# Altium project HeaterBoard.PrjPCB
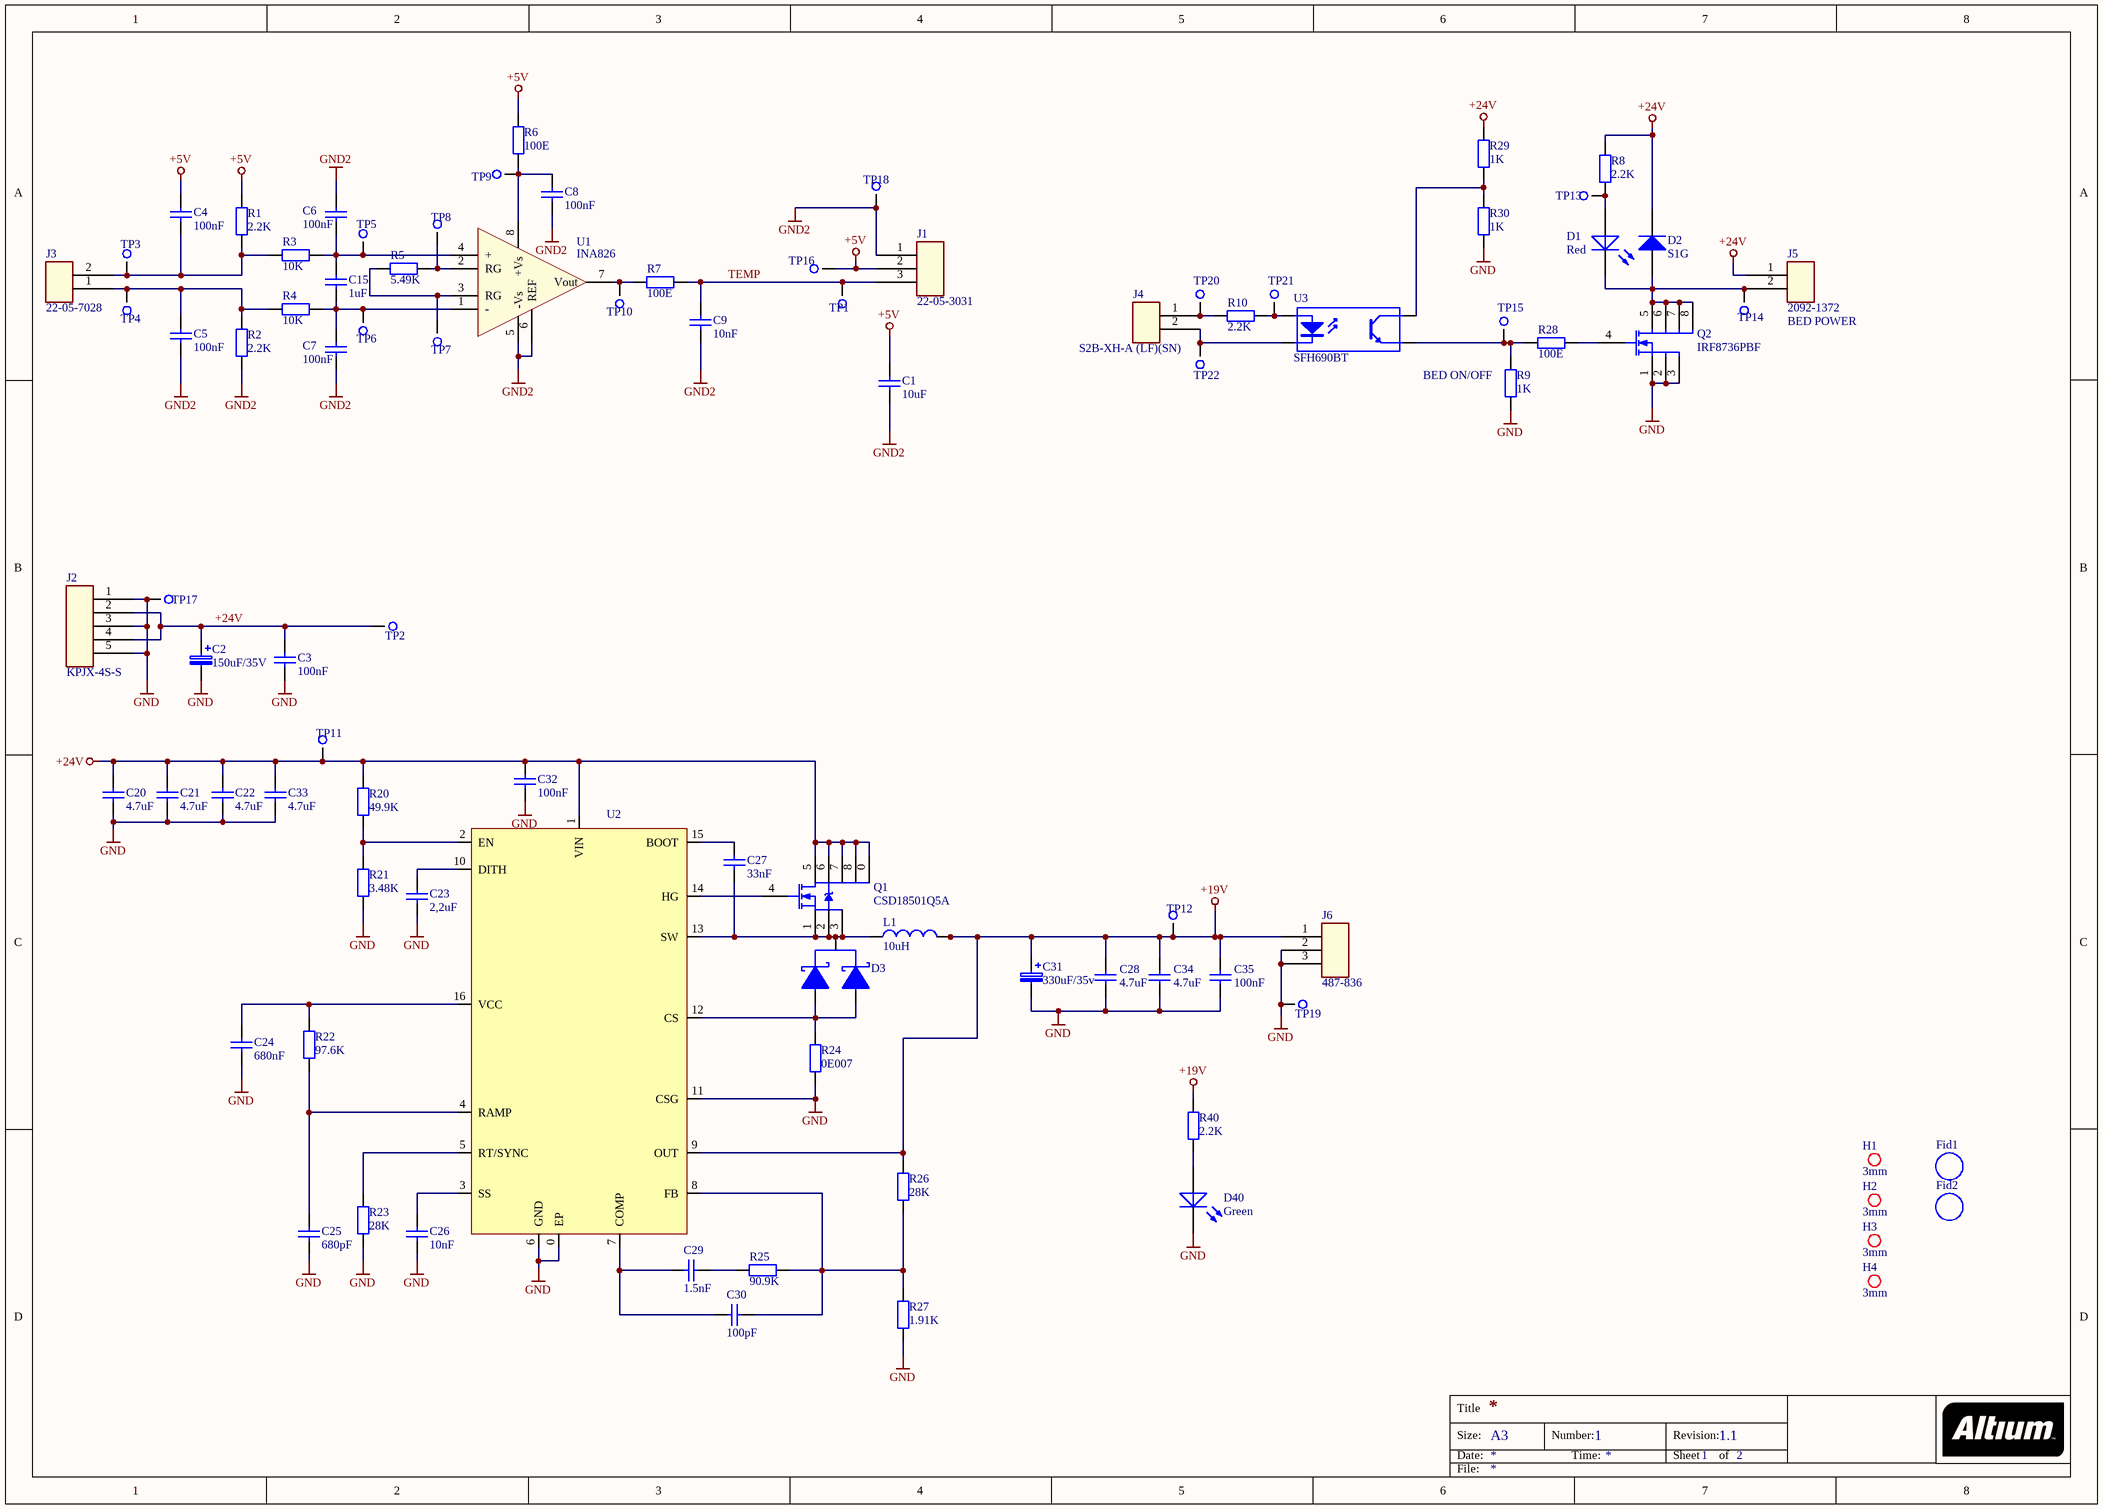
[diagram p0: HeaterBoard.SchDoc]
1 sheet, 92 parts. Net scope: global (net labels, ports and power ports of the same name join across sheets).
Board file: HeaterBoard.PcbDoc

## Sheet HeaterBoard.SchDoc
size A3; ApprovedBy: CdB; CheckedBy: CdB; DrawnBy: RT; Engineer: CdB; DocumentNumber: 1; Revision: 1.1; SheetNumber: 1; SheetTotal: 2; Status: Final

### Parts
C1  10uF  [C1206 (3216)]
C2  150uF/35V  [ELCO Case F]
C3  100nF  [C0805 (2012)]
C4  100nF  [C0805 (2012)]
C5  100nF  [C0805 (2012)]
C6  100nF  [C0805 (2012)]
C7  100nF  [C0805 (2012)]
C8  100nF  [C0805 (2012)]
C9  10nF  [C0805 (2012)]
C15  1uF  [C0603 (1608)]
C20  4.7uF  [C1206 (3216)]
C21  4.7uF  [C1206 (3216)]
C22  4.7uF  [C1206 (3216)]
C23  2,2uF  [C0603 (1608)]
C24  680nF  [C0603 (1608)]
C25  680pF  [C0603 (1608)]
C26  10nF  [C0603 (1608)]
C27  33nF  [C0805 (2012)]
C28  4.7uF  [C1206 (3216)]
C29  1.5nF  [C0603 (1608)]
C30  100pF  [C0603 (1608)]
C31  330uF/35v  [ELCO Case G]
C32  100nF  [C0805 (2012)]
C33  4.7uF  [C1206 (3216)]
C34  4.7uF  [C1206 (3216)]
C35  100nF  [C0805 (2012)]
D1  Red  [LED0805-RED]
D2  S1G  [DIODE DO214AC (SMA)]
D3  Diode Dual Schottky MBRB1545 45V 15A  [DIODE D2PAK(Case 418B)]  (value not drawn)
D40  Green  [LED0805-GREEN]
Fid1  Fiducial  [Fiducial 1,5mm]  (value not drawn)  (no BOM)
Fid2  Fiducial  [Fiducial 1,5mm]  (value not drawn)  (no BOM)
H1  3mm  [Mounting Hole 3mm NPTH]  (no BOM)
H2  3mm  [Mounting Hole 3mm NPTH]  (no BOM)
H3  3mm  [Mounting Hole 3mm NPTH]  (no BOM)
H4  3mm  [Mounting Hole 3mm NPTH]  (no BOM)
J1  22-05-3031  [HEADER 3P RIGHT ANGLE]
J2  KPJX-4S-S  [Con KPJX-4S-S]
J3  22-05-7028  [HEADER 2P RIGHT ANGLE]
J4  S2B-XH-A (LF)(SN)  [CON S2B-XH-A (LF)(SN)]
J5  2092-1372  [Con 2092-1372]
J6  487-836  [Con DC Power Socket]
L1  10uH  [Inductor XAL1010-103MEB]
Q1  CSD18501Q5A  [IC SON5x6]
Q2  IRF8736PBF  [IC SOIC-8]
R1  2.2K  [R0805 (2012)]
R2  2.2K  [R0805 (2012)]
R3  10K  [R0805 (2012)]
R4  10K  [R0805 (2012)]
R5  5.49K  [R0603 (1608)]
R6  100E  [R0805 (2012)]
R7  100E  [R0805 (2012)]
R8  2.2K  [R0805 (2012)]
R9  1K  [R0805 (2012)]
R10  2.2K  [R0805 (2012)]
R20  49.9K  [R0603 (1608)]
R21  3.48K  [R0603 (1608)]
R22  97.6K  [R0603 (1608)]
R23  28K  [R0603 (1608)]
R24  0E007  [R1632X06N]
R25  90.9K  [R0603 (1608)]
R26  28K  [R0603 (1608)]
R27  1.91K  [R0603 (1608)]
R28  100E  [R0805 (2012)]
R29  1K  [R0805 (2012)]
R30  1K  [R0805 (2012)]
R40  2.2K  [R0805 (2012)]
TP1  2mm  [TESTPOINT 2mm]  (value not drawn)  (no BOM)
TP2  2mm  [TESTPOINT 2mm]  (value not drawn)  (no BOM)
TP3  2mm  [TESTPOINT 2mm]  (value not drawn)  (no BOM)
TP4  2mm  [TESTPOINT 2mm]  (value not drawn)  (no BOM)
TP5  2mm  [TESTPOINT 2mm]  (value not drawn)  (no BOM)
TP6  2mm  [TESTPOINT 2mm]  (value not drawn)  (no BOM)
TP7  2mm  [TESTPOINT 2mm]  (value not drawn)  (no BOM)
TP8  2mm  [TESTPOINT 2mm]  (value not drawn)  (no BOM)
TP9  2mm  [TESTPOINT 2mm]  (value not drawn)  (no BOM)
TP10  2mm  [TESTPOINT 2mm]  (value not drawn)  (no BOM)
TP11  2mm  [TESTPOINT 2mm]  (value not drawn)  (no BOM)
TP12  2mm  [TESTPOINT 2mm]  (value not drawn)  (no BOM)
TP13  2mm  [TESTPOINT 2mm]  (value not drawn)  (no BOM)
TP14  2mm  [TESTPOINT 2mm]  (value not drawn)  (no BOM)
TP15  2mm  [TESTPOINT 2mm]  (value not drawn)  (no BOM)
TP16  2mm  [TESTPOINT 2mm]  (value not drawn)  (no BOM)
TP17  2mm  [TESTPOINT 2mm]  (value not drawn)  (no BOM)
TP18  2mm  [TESTPOINT 2mm]  (value not drawn)  (no BOM)
TP19  2mm  [TESTPOINT 2mm]  (value not drawn)  (no BOM)
TP20  2mm  [TESTPOINT 2mm]  (value not drawn)  (no BOM)
TP21  2mm  [TESTPOINT 2mm]  (value not drawn)  (no BOM)
TP22  2mm  [TESTPOINT 2mm]  (value not drawn)  (no BOM)
U1  INA826  [IC MSOP8]
U2  LM25088MH-1  [IC HTSSOP-16]  (value not drawn)
U3  SFH690BT  [IC SOP-4]

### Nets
+5V: C1.2 C4.1 J1.2 R1.2 R6.2 TP16.1
+19V: C28.2 C31.1 C34.2 C35.1 J6.1 L1.2 R26.2 R40.2 TP12.1 U2.9(OUT)
+24V: C2.1 C3.1 C20.2 C21.2 C22.2 C32.1 C33.2 D2.2(K) J2.2 J2.4 J5.1 Q1.0(D) Q1.5(D) Q1.6(D) Q1.7(D) Q1.8(D) R8.2 R20.2 R29.2 TP2.1 TP11.1 U2.1(VIN)
GND: C2.2 C3.2 C20.1 C21.1 C22.1 C23.1 C24.1 C25.1 C26.1 C28.1 C31.2 C32.2 C33.1 C34.1 C35.2 D40.2(K) J2.1 J2.3 J2.5 J6.2 J6.3 Q2.1(S) Q2.2(S) Q2.3(S) R9.1 R21.1 R23.1 R24.1 R27.1 R30.2 TP17.1 TP19.1 U2.0(EP) U2.6(GND) U2.11(CSG)
GND2: C1.1 C5.2 C6.1 C7.2 C8.2 C9.1 J1.1 R2.1 TP18.1 U1.5(-Vs) U1.6(REF)
TEMP: C9.2 J1.3 R7.1 TP1.1
NetC4_2: C4.2 J3.2 R1.1 R3.1 TP3.1
NetC5_1: C5.1 J3.1 R2.2 R4.1 TP4.1
NetC6_2: C6.2 C15.2 R3.2 TP5.1 U1.4(+)
NetC7_1: C7.1 C15.1 R4.2 TP6.1 U1.1(-)
NetC8_1: C8.1 R6.1 TP9.1 U1.8(+Vs)
NetC23_2: C23.2 U2.10(DITH)
NetC24_2: C24.2 R22.2 U2.16(VCC)
NetC25_2: C25.2 R22.1 U2.4(RAMP)
NetC26_2: C26.2 U2.3(SS)
NetC27_1: C27.1 D3.4(K) L1.1 Q1.1(S) Q1.2(S) Q1.3(S) U2.13(SW)
NetC27_2: C27.2 U2.15(BOOT)
NetC29_1: C29.1 C30.1 U2.7(COMP)
NetC29_2: C29.2 R25.1
NetC30_2: C30.2 R25.2 R26.1 R27.2 U2.8(FB)
NetD1_1: D1.1(A) R8.1 TP13.1
NetD1_2: D1.2(K) D2.1(A) J5.2 Q2.5(D) Q2.6(D) Q2.7(D) Q2.8(D) TP14.1
NetD3_1: D3.1(A) D3.3(A) R24.2 U2.12(CS)
NetD40_1: D40.1(A) R40.1
NetJ4_1: J4.1 R10.1 TP20.1
NetJ4_2: J4.2 TP22.1 U3.2(K)
NetQ1_4: Q1.4 U2.14(HG)
NetQ2_4: Q2.4(G) R28.2
NetR5_1: R5.1 TP7.1 U1.3(RG)
NetR5_2: R5.2 TP8.1 U1.2(RG)
NetR7_2: R7.2 TP10.1 U1.7(Vout)
NetR9_2: R9.2 R28.1 TP15.1 U3.3(E)
NetR10_2: R10.2 TP21.1 U3.1(A)
NetR20_1: R20.1 R21.2 U2.2(EN)
NetR23_2: R23.2 U2.5(RT/SYNC)
NetR29_1: R29.1 R30.1 U3.4(C)

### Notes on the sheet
- BED ON/OFF
- (near J5) BED POWER

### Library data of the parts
C1 = Cap 10uF X7R 1206: Cap 10uF X7R 1206  10% 25V; Faber ItemCode: 35605200; Mfg: SAMSUNG; Mfg code: CL31B1076KAHNNNE; Faber Artikelomschrijving: X7R 10uF 10% 25V 1206; Bestel grote: 2000; Prijs: 0,0218
C2 = Cap Elco 150uF 35V: Cap elco 150uF 35V case F  EEHZA1 PAN; Value: 135uF/35V; Bestel grote: 10; Mfg: PANASONIC; Mfg code: EEHZA1V151P; Prijs: 2,03
C3-C8 C32 C35 = Cap 100nF X7R 0805: Cap 100nF X7R 0805 10% 50V; Faber ItemCode: 31219200; Mfg: PHYCOMP; Mfg code: 2238 580 15649; Faber Artikelomschrijving: X7R 100nF 10% 50V 0805; Bestel grote: 4000; Prijs: 0,0032
C9 = Cap 10nF X7R 0805: Cap 10nF X7R 0805 10% 50V; Faber ItemCode: 30873000; Mfg: PHYCOMP; Mfg code: 2238 580 15636; Faber Artikelomschrijving: X7R 10nF 10% 50V 0805; Bestel grote: 24000; Prijs: 0,002
C15 = Cap 1uF X5R 0603: Cap 1uF X5R 0603 10% 10V; Faber ItemCode: 36310600; Faber Artikelomschrijving: X5R 1uF 10% 10V 0603; Prijs: 0,0028
C20-C22 C28 C33 C34 = Cap 4.7uF 50V X7R 1206: Cap 4.7uF X7R 1206 10% 50V; Mfg: MURATA; Mfg code: GRM31CR71H475KA12L; Bestel grote: 10; Prijs: 0,49
C23 = Cap 2,2uF X7R 0603: Cap 2,2uF X7R 0603 10% 6,3V; Faber ItemCode: 35496900; Faber Artikelomschrijving: X7R 2,2UF 10% 6,3V 0603; Prijs: 0,0081
C24 = Cap 680nF X7R 0603: Cap 680nF X7R 0603 10% 16V; Faber ItemCode: 35550500; Faber Artikelomschrijving: X7R 680NF 10% 16V 0603; Prijs: 0,124
C25 = Cap 680pF X7R 0603: Cap 680pF NPO 0603 5% 50V; Mfg: MULTICOMP; Mfg code: MC0603N681J500CT; Bestel grote: 10; Prijs: 0,013
C26 = Cap 10nF X7R 0603: Cap 10nF X7R 0603 10% 50V; Mfg: MULTICOMP; Mfg code: U0603R103KCT; Bestel grote: 10; Prijs: 0,021
C27 = Cap 33nF X7R 0805: Cap 33nF X7R 0805 10% 50V; Mfg: MULTICOMP; Mfg code: MC0805B333J500CT; Bestel grote: 10; Prijs: 0,027
C29 = Cap 1.5nF X7R 0603: Cap 1.5nF X7R 0603 5% 50V; Mfg: MULTICOMP; Mfg code: MC0603B152J500CT; Bestel grote: 10; Prijs: 0,017
C30 = Cap 100pF X7R 0603: Cap 100pF X7R 0603 5% 50V; Mfg: AVX; Mfg code: 06035C101JAT2A; Prijs: 0,139
C31 = Cap Elco 330uF 35V: Cap elco 330uF 35V case G UD Nichicon; Bestel grote: 1; Mfg code: UUD1V331MNL1GS; Prijs: 0,65
D1 = LED HSMH-C170: LED ROOD HSMH-C170 0805 AVAGO; Bestel grote: 5; Prijs: 0,195
D2 = Diode S1G: Diode S1G DO-214AC 400V 1A; Faber ItemCode: 32284000; Mfg: MULTICOMP; Prijs: 0,017
D3 = Diode MBRB1545: MBRB1545; Bestel grote: 1; Mfg: ON SEMICONDUCTOR; Mfg code: MBRB1545CTG; Prijs: 1,16
D40 = LED HSMG-C170: LED GROEN HSMG-C170 0805 AVAGO; Faber ItemCode: 35162200; Bestel grote: 5; Prijs: 0,115; Faber locatie: 20 BS5B
Fid1 Fid2 = Fiducial: Remarks: Not a component
H1-H4 = Mounting Hole 3mm NPTH: Remarks: Not a component
J1 = Header 3p r.a.: Header 3p right angle 22-05-3031 Molex; Bestel grote: 1; Prijs: 0,45
J2 = Connector KPJX-4S-S: Connector 5p KPJX-4S-S KYCON; Faber ItemCode: 36925000; Faber Artikelomschrijving: CONN PR THT KPJX-4S-S KYCON; Bestel grote: 1; Prijs: 3,19
J3 = Header 2p r.a.: Header 2p right angle 22-05-7028 Molex; Bestel grote: 5; Prijs: 0,78
J4 = Connector S2B-XH-A (LF)(SN): Connector S2B-XH-A (LF)(SN)  2p r.a.; Faber ItemCode: 36926700; Mfg: JST; Faber Artikelomschrijving: RO CONN PR 2p HKS S2B-XH-A (LF)(SN) JST
J5 = Connector 2092-1372 2p: Connector 2092-1372 2p therm Block r.a.; Mfg: Wago; Bestel grote: 5; Prijs: 0,88
J6 = Connector DC Power Socket: DC Power Socket 2.5mm Right Angle PCB Mount; Mfg: RS; Bestel grote: 1; Prijs: 2,55
L1 = Inductor 10uH SMD: Inductor 10uH 11A SMD; Mfg: Coilcraft; Mfg code: XAL1010-103MEB
Q1 = MOSFET-N CSD18501Q5A: MOSFET-N CSD18501Q5A 40V 100A; Bestel grote: 1; Mfg: Texas Instruments
Q2 = MOSFET-N IRF8736PBF: MOSFET-N IRF8736PBF 30V 18A; Mfg: INTERNATIONAL RECTIFIER; Faber ItemCode: 36926000; Prijs: 0,82
R1 R2 R8 R10 R40 = Res 2.2K 0805: Res 2.2K 0805 1% 100mW; Mfg: MULTICOMP; Mfg code: MC01W080512K2; Bestel grote: 50; Prijs: 0,0019
R3 R4 = Res 10K 0805: Res 10K 0805 1% 100mW; Mfg: MULTICOMP; Mfg code: MC01W0805110K
R5 = Res 5.49K 0603: Res 5.49K 0603 1% 63mW; Faber ItemCode: 36926200; Mfg: WELWYN; Faber Artikelomschrijving: RES 5K49 0,1% 0,063W 25ppm 0603 PCF0603R 5K49B.T1 WELWYN; Prijs: 0,0591
R6 R7 R28 = Res 100E 0805: Res 100E 0805 1% 125mW; Faber ItemCode: 31560100; Mfg: YAGEO; Mfg code: WRC31022/ RC0805FR-07100RL; Faber Artikelomschrijving: RES 100E 1% 0,125W 0805; Bestel grote: 5000; Prijs: 0,0009
R9 R29 R30 = Res 1K 0805: Res 1K 0805 1% 100mW; Mfg: MULTICOMP; Mfg code: MC01W080511K; Bestel grote: 50
R20 = Res 49.9K 0603: Res 49.9K 0603 1% 63mW; Faber ItemCode: 36215400; Faber Artikelomschrijving: RES 49k9 1% 0,063W 0603; Prijs: 0,0006
R21 = Res 3.48K 0603: Res 3.48K 0603 1% 63mW; Faber ItemCode: 36977100; Faber Artikelomschrijving: RES 3k48 1% 0,063W 0603; Prijs: 0,0006
R22 = Res 97.6K 0603: Res 97.6K 0603 1% 63mW; Mfg: MULTICOMP; Mfg code: MC0063W0603197K6; Bestel grote: 50; Prijs: 0,017
R23 R26 = Res 28K 0603: Res 28K 0603 1% 63mW; Mfg: MULTICOMP; Mfg code: MC0063W0603128K; Bestel grote: 50; Prijs: 0,017
R24 = Res 0E007 1632: Res 0E007 1632 1% 1W; Mfg: Susumu; Mfg code: PRL1632-R007-F-T1; Bestel grote: 5; Prijs: 0,872
R25 = Res 90.9K 0603: Res 90.9K 0603 1% 63mW; Mfg: MULTICOMP; Mfg code: MC0063W0603190K9; Bestel grote: 50; Prijs: 0,017
R27 = Res 1.91K 0603: Res 1.91K 0603 1% 63mW; Mfg: MULTICOMP; Mfg code: MC0063W060311K91; Bestel grote: 50; Prijs: 0,017
TP1-TP22 = Testpoint, 2mm, round: Remarks: Not a component
U1 = IC INA826: IC OP AMP, instr, 1MHz; Mfg: Texas Instruments; Mfg code: INA826AIDGKR; Bestel grote: 1; Prijs: 1,17
U2 = IC LM25088MH-1: IC DC-DC Buck Controller; Mfg: Texas Instruments; Mfg code: LM25088MH-1/NOPB
U3 = Opto SFH690BT: Opto SFH690BT SOP-4; Bestel grote: 1; Faber Artikelomschrijving: OPTO SFH690BT SO-04 VISHAY; Faber ItemCode: 35549100; Mfg: VISHAY SEMICONDUCTOR; Mfg code: 1469595RL; Prijs: 0,69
